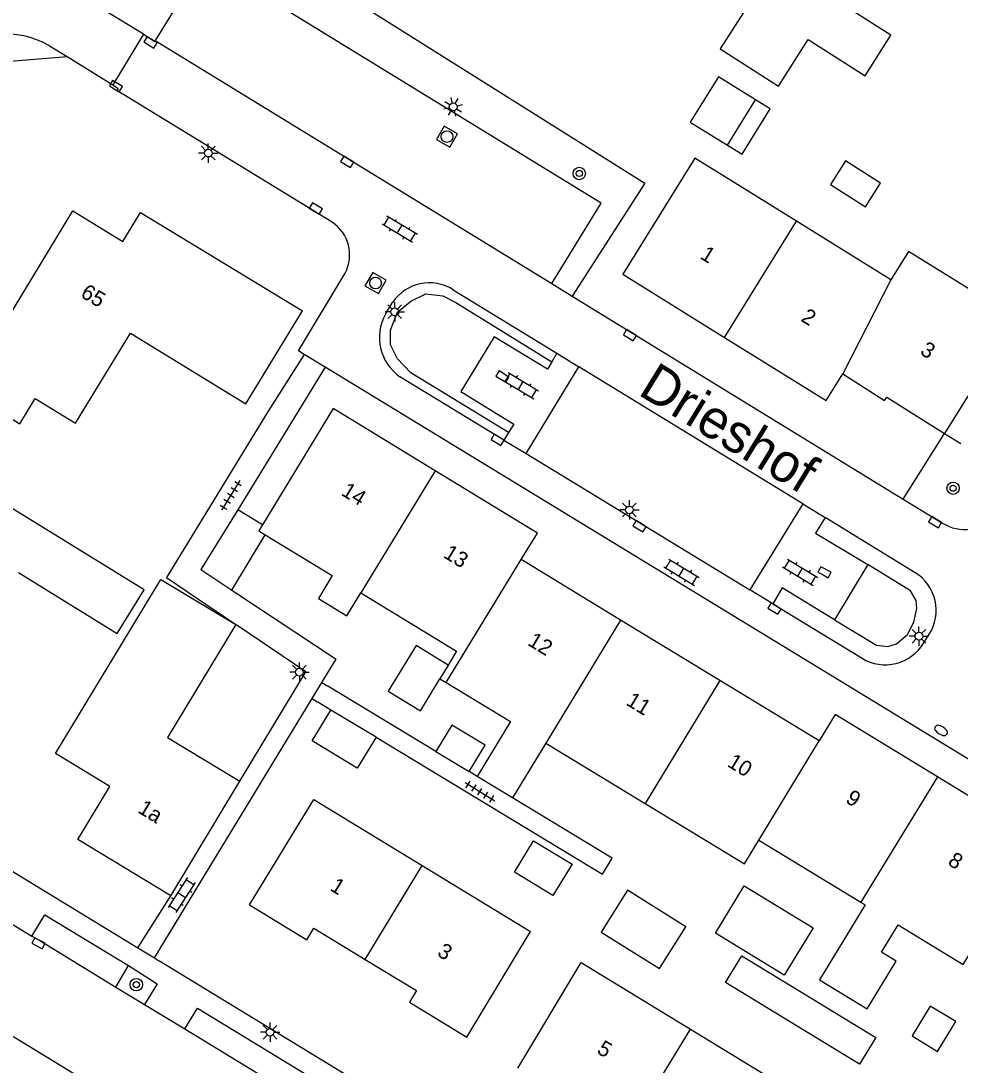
# Model space of a CAD drawing. Extents: x 136000 to 141014, y 402000 to 403500.
# Drawn here: x 137702.6 to 137763.2, y 402099.2 to 402166.6 of the extents above; entities that cross this region are included whole.
import ezdxf

# ---------------------------------------------------------------- set-up
doc = ezdxf.new("R2010")
doc.units = 0
for name, color, linetype in [('gg-afsc-erfafscheiding', 7, 'Continuous'), ('gg-afsc-muur', 7, 'Continuous'), ('gg-anno-huisnummerreeks BGT', 7, 'Continuous'), ('gg-anno-openbare ruimte label', 7, 'Continuous'), ('gg-bbg-gedigitaliseerde bebouwing', 7, 'Continuous'), ('gg-bbg-gedigitaliseerde bijgebouw', 7, 'Continuous'), ('gg-bbg-hoofdgebouw', 7, 'Continuous'), ('gg-bbg-luifel en loopbrug', 7, 'Continuous'), ('gg-bbg-tussenscheiding', 7, 'Continuous'), ('gg-knt-verharding', 7, 'Continuous'), ('gg-knt-verharding nz', 7, 'Continuous'), ('gt-grn-groengrens', 7, 'Continuous'), ('gt-symb-boom', 7, 'Continuous'), ('gt-symb-brandkraan', 7, 'Continuous'), ('gt-symb-klinker verharding', 7, 'Continuous'), ('gt-symb-kolk', 7, 'Continuous'), ('gt-symb-lichtmast', 7, 'Continuous'), ('gt-symb-rioolschacht', 7, 'Continuous'), ('gt-symb-tegel verharding', 7, 'Continuous')]:
    doc.layers.add(name, color=color, linetype=linetype)

# ---------------------------------------------------------------- blocks, each defined once
blk = doc.blocks.new('gt0-LMAST')
at = {"layer": 'gt-symb-lichtmast'}
for p, q in [((-0.182, 0.173), (-0.447, 0.438)), ((-0.005, 0.246), (-0.005, 0.621)), ((0.172, 0.173), (0.437, 0.438)), ((-0.255, -0.004), (-0.63, -0.004)), ((-0.182, -0.181), (-0.447, -0.446)), ((-0.005, -0.254), (-0.005, -0.629)), ((0.437, -0.446), (0.172, -0.181)), ((0.245, -0.004), (0.62, -0.004))]:
    blk.add_line(p, q, dxfattribs=at)
blk.add_circle((-0.005, -0.004), 0.25, dxfattribs=at)
blk = doc.blocks.new('gt0-KOLK')
at = {"layer": 'gt-symb-kolk'}
blk.add_lwpolyline([(0, 0), (0.375, 0), (0.375, 0.4), (-0.375, 0.4), (-0.375, 0), (0, 0)], dxfattribs=at)
blk = doc.blocks.new('gt0-BOOM')
at = {"layer": 'gt-symb-boom'}
for radius in [0.4, 0.2]:
    blk.add_circle((0, 0), radius, dxfattribs=at)
blk = doc.blocks.new('gt0-KL1')
at = {"layer": 'gt-symb-klinker verharding'}
for p, q in [((-1.15, 0.3), (1.15, 0.3)), ((-1, -0.3), (-1, 0.3)), ((-0.5, 0.3), (-0.5, 0.45)), ((0, -0.3), (0, 0.3)), ((0.5, 0.3), (0.5, 0.45)), ((1, -0.3), (1, 0.3)), ((-1.15, -0.3), (1.15, -0.3)), ((-0.5, -0.45), (-0.5, -0.3)), ((0.5, -0.45), (0.5, -0.3))]:
    blk.add_line(p, q, dxfattribs=at)
blk = doc.blocks.new('gt0-RS')
at = {"layer": 'gt-symb-rioolschacht'}
blk.add_lwpolyline([(-0.5, -0.5), (0.5, -0.5), (0.5, 0.5), (-0.5, 0.5)], close=True, dxfattribs=at)
blk.add_circle((0, 0), 0.375, dxfattribs=at)
blk = doc.blocks.new('gt0-TEG1')
at = {"layer": 'gt-symb-tegel verharding'}
for p, q in [((-1.125, 0), (1.125, 0)), ((-0.9, -0.25), (-0.9, 0.25)), ((-0.45, -0.25), (-0.45, 0.25)), ((0, -0.25), (0, 0.25)), ((0.45, -0.25), (0.45, 0.25)), ((0.9, -0.25), (0.9, 0.25))]:
    blk.add_line(p, q, dxfattribs=at)
blk = doc.blocks.new('gt0-BR')
at = {"layer": 'gt-symb-brandkraan'}
for centre, radius, start, end in [((-0.244, 0), 0.206, 107.56694, 252.43307), ((0.599, -2.664), 3, 106.89205, 107.56694), ((0, -0.691), 0.938, 73.10799, 106.89205), ((-0.599, -2.664), 3, 72.43309, 73.10799), ((0.244, 0), 0.206, 287.56695, 72.43309), ((0.599, 2.664), 3, 252.43307, 253.10797), ((0, 0.691), 0.938, 253.10797, 286.89206), ((-0.599, 2.664), 3, 286.89206, 287.56695)]:
    blk.add_arc(centre, radius, start, end, dxfattribs=at)

msp = doc.modelspace()

# ---------------------------------------------------------------- linework, layer by layer
at = {"layer": 'gg-afsc-erfafscheiding'}
for p, q in [((137759.538, 402135.743), (137762.2, 402139.97)), ((137722.009, 402123.896), (137722.384, 402123.668)), ((137729.368, 402119.445), (137722.384, 402123.668)), ((137721.377, 402122.858), (137721.75, 402122.631)), ((137722.594, 402122.12), (137721.75, 402122.631)), ((137732.036, 402117.837), (137731.514, 402118.146))]:
    msp.add_line(p, q, dxfattribs=at)
for points in [[(137708.781, 402177.581), (137742.867, 402156.136), (137738.168, 402148.849)], [(137725.504, 402120.36), (137740.115, 402111.522), (137740.744, 402112.563), (137734.318, 402116.45)]]:
    msp.add_lwpolyline(points, dxfattribs=at)
at = {"layer": 'gg-afsc-muur'}
msp.add_line((137718.534, 402141.413), (137711.967, 402130.672), dxfattribs=at)
msp.add_lwpolyline([(137716.722, 402117.516), (137720.971, 402124.59), (137716.45, 402127.636)], dxfattribs=at)
at = {"layer": 'gg-bbg-gedigitaliseerde bebouwing'}
for p, q in [((137758.738, 402149.902), (137752.648, 402153.682)), ((137722.73, 402141.59), (137718.165, 402134.085)), ((137729.625, 402124.145), (137730.032, 402123.898)), ((137736.467, 402119.988), (137734.318, 402116.45)), ((137736.467, 402119.988), (137742.879, 402116.092)), ((137734.318, 402116.45), (137732.036, 402117.837)), ((137750.219, 402113.707), (137756.808, 402109.703)), ((137728.493, 402112.076), (137735.475, 402107.829)), ((137756.808, 402109.703), (137757.078, 402109.539)), ((137738.758, 402105.815), (137745.816, 402101.502))]:
    msp.add_line(p, q, dxfattribs=at)
for points in [[(137752.648, 402153.682), (137746.077, 402157.76), (137741.43, 402150.26)], [(137766.83, 402147.42), (137759.877, 402151.738), (137758.738, 402149.902)], [(137697.2, 402143.82), (137702.504, 402140.61), (137703.498, 402142.239), (137706.099, 402140.651), (137709.643, 402146.457), (137717.104, 402141.903), (137720.75, 402147.89)], [(137702.415, 402131.006), (137708.801, 402127.065), (137710.537, 402129.877), (137701.28, 402135.59)], [(137718.355, 402133.436), (137722.679, 402130.808), (137721.782, 402129.332), (137723.624, 402128.213), (137724.521, 402129.689)], [(137724.521, 402129.689), (137730.709, 402125.929), (137730.16, 402125.026)], [(137730.032, 402123.898), (137734.185, 402121.374), (137732.036, 402117.837)], [(137717.34, 402109.55), (137721.498, 402116.346), (137728.493, 402112.076)], [(137742.879, 402116.092), (137749.298, 402112.192), (137750.219, 402113.707)], [(137759.21, 402108.243), (137763.417, 402105.687), (137768.35, 402113.78)], [(137757.078, 402109.539), (137754.14, 402104.702), (137757.213, 402102.835), (137759.081, 402105.909), (137758.139, 402106.48), (137759.21, 402108.243)], [(137745.816, 402101.502), (137752.819, 402097.23), (137748.66, 402090.43)]]:
    msp.add_lwpolyline(points, dxfattribs=at)
at = {"layer": 'gg-bbg-gedigitaliseerde bijgebouw'}
for p, q in [((137748.187, 402158.6), (137750.001, 402161.528)), ((137745.791, 402160.085), (137748.187, 402158.6)), ((137718.165, 402134.085), (137716.573, 402135.052)), ((137716.188, 402129.87), (137718.355, 402133.436)), ((137725.504, 402120.36), (137722.594, 402122.12)), ((137729.368, 402119.445), (137731.514, 402118.146))]:
    msp.add_line(p, q, dxfattribs=at)
for points in [[(137747.727, 402164.807), (137751.493, 402162.405), (137753.409, 402165.41), (137757.073, 402163.074), (137758.748, 402165.701), (137751.318, 402170.439), (137747.727, 402164.807)], [(137750.001, 402161.528), (137747.605, 402163.013), (137745.791, 402160.085)], [(137755.82, 402157.589), (137754.84, 402156.052), (137757.1, 402154.612), (137758.08, 402156.149), (137755.82, 402157.589)], [(137716.573, 402135.052), (137714.204, 402131.185), (137716.188, 402129.87)], [(137730.16, 402125.026), (137728.09, 402126.283), (137726.295, 402123.33), (137728.365, 402122.072), (137729.625, 402124.145)], [(137725.504, 402120.36), (137724.296, 402118.363), (137721.386, 402120.123), (137722.594, 402122.12)], [(137731.514, 402118.146), (137732.546, 402119.845), (137730.402, 402121.147), (137729.368, 402119.445)], [(137734.437, 402111.647), (137735.674, 402113.684), (137738.16, 402112.173), (137736.923, 402110.137), (137734.437, 402111.647)], [(137741.739, 402110.481), (137740.047, 402107.777), (137743.809, 402105.423), (137745.501, 402108.127), (137741.739, 402110.481)], [(137747.412, 402107.711), (137749.266, 402110.763), (137753.715, 402108.06), (137751.859, 402105.004), (137747.412, 402107.711)], [(137748.068, 402104.518), (137749.119, 402106.244), (137757.769, 402100.978), (137756.718, 402099.252), (137748.068, 402104.518)], [(137760.112, 402101.074), (137761.759, 402100.073), (137762.934, 402102.006), (137761.286, 402103.007), (137760.112, 402101.074)]]:
    msp.add_lwpolyline(points, dxfattribs=at)
at = {"layer": 'gg-bbg-hoofdgebouw'}
for p, q in [((137741.43, 402150.26), (137747.995, 402146.185)), ((137766.83, 402147.42), (137762.2, 402139.97)), ((137729.325, 402137.57), (137722.73, 402141.59)), ((137741.293, 402127.933), (137734.88, 402131.83)), ((137747.706, 402124.037), (137741.293, 402127.933)), ((137754.12, 402120.14), (137747.706, 402124.037)), ((137768.35, 402113.78), (137761.75, 402117.805)), ((137712.248, 402110.125), (137716.722, 402117.516)), ((137731.36, 402101), (137735.475, 402107.829)), ((137734.65, 402098.99), (137738.758, 402105.815))]:
    msp.add_line(p, q, dxfattribs=at)
for points in [[(137697.2, 402143.82), (137700.07, 402148.55), (137701.78, 402147.5), (137705.94, 402154.35), (137709.15, 402152.38), (137710.29, 402154.25), (137720.75, 402147.89)], [(137747.995, 402146.185), (137754.56, 402142.11), (137755.63, 402143.82)], [(137755.63, 402143.82), (137758.33, 402142.1), (137758.48, 402142.32), (137762.2, 402139.97)], [(137734.88, 402131.83), (137735.92, 402133.55), (137729.325, 402137.57)], [(137712.248, 402110.125), (137706.248, 402113.757), (137708.312, 402117.188), (137704.808, 402119.306), (137711.616, 402130.56), (137716.45, 402127.636)], [(137716.45, 402127.636), (137712.042, 402120.349), (137716.722, 402117.516)], [(137761.75, 402117.805), (137755.15, 402121.83), (137754.12, 402120.14)], [(137717.34, 402109.55), (137721.04, 402107.29), (137721.49, 402108.03), (137724.802, 402106.017)], [(137724.802, 402106.017), (137728.12, 402104), (137727.66, 402103.25), (137731.36, 402101)]]:
    msp.add_lwpolyline(points, dxfattribs=at)
at = {"layer": 'gg-bbg-luifel en loopbrug'}
msp.add_lwpolyline([(137748.187, 402158.6), (137749.14, 402158.01), (137750.954, 402160.938), (137750.001, 402161.528)], dxfattribs=at)
at = {"layer": 'gg-bbg-tussenscheiding'}
for p, q in [((137747.995, 402146.185), (137752.648, 402153.682)), ((137758.738, 402149.902), (137755.63, 402143.82)), ((137729.325, 402137.57), (137724.521, 402129.689)), ((137730.032, 402123.898), (137734.88, 402131.83)), ((137741.293, 402127.933), (137736.467, 402119.988)), ((137730.16, 402125.026), (137729.625, 402124.145)), ((137747.706, 402124.037), (137742.879, 402116.092)), ((137750.219, 402113.707), (137754.12, 402120.14)), ((137761.75, 402117.805), (137756.808, 402109.703)), ((137724.802, 402106.017), (137728.493, 402112.076)), ((137742.11, 402095.454), (137745.816, 402101.502))]:
    msp.add_line(p, q, dxfattribs=at)
msp.add_lwpolyline([(137718.165, 402134.085), (137717.928, 402133.695), (137718.355, 402133.436)], dxfattribs=at)
at = {"layer": 'gg-knt-verharding'}
for p, q in [((137710.484, 402165.757), (137707.524, 402167.564)), ((137710.484, 402165.757), (137708.513, 402162.494)), ((137705.559, 402164.312), (137708.513, 402162.494)), ((137722.666, 402153.626), (137708.781, 402162.134)), ((137736.854, 402149.655), (137738.168, 402148.849)), ((137730.489, 402149.25), (137737.17, 402145.158)), ((137738.168, 402148.849), (137759.538, 402135.743)), ((137726.109, 402147.679), (137726.57, 402148.43)), ((137720.861, 402145.084), (137718.534, 402141.413)), ((137722.213, 402144.26), (137720.861, 402145.084)), ((137737.17, 402145.158), (137736.852, 402144.609)), ((137722.213, 402144.26), (137716.573, 402135.052)), ((137735.194, 402138.676), (137738.594, 402144.286)), ((137753.057, 402135.426), (137738.594, 402144.286)), ((137733.75, 402139.557), (137727.05, 402143.64)), ((137734.057, 402140.041), (137733.75, 402139.557)), ((137735.194, 402138.676), (137749.638, 402129.874)), ((137753.057, 402135.426), (137749.638, 402129.874)), ((137759.538, 402135.743), (137762.07, 402134.19)), ((137760.3, 402130.99), (137754.493, 402134.547)), ((137757.251, 402131.513), (137755.094, 402127.95)), ((137711.967, 402130.672), (137716.45, 402127.636)), ((137716.188, 402129.87), (137722.926, 402125.403)), ((137751.114, 402128.974), (137756.88, 402125.46)), ((137760.86, 402126.45), (137761.21, 402127.011)), ((137722.009, 402123.896), (137722.926, 402125.403)), ((137721.377, 402122.858), (137722.009, 402123.896)), ((137711.195, 402106.122), (137721.377, 402122.858)), ((137688.732, 402119.823), (137710.129, 402106.77)), ((137696.701, 402111.528), (137703.294, 402107.516)), ((137710.129, 402106.77), (137712.248, 402110.125)), ((137710.129, 402106.77), (137711.195, 402106.122)), ((137708.71, 402104.22), (137709.528, 402105.613)), ((137711.195, 402106.122), (137711.532, 402105.913)), ((137785.32, 402060.9), (137711.532, 402105.913)), ((137708.71, 402104.22), (137710.56, 402103.109)), ((137713.041, 402094.346), (137698.901, 402102.965)), ((137710.56, 402103.109), (137713.151, 402101.525))]:
    msp.add_line(p, q, dxfattribs=at)
for points in [[(137736.854, 402149.655), (137740.043, 402154.855), (137714.443, 402170.555), (137711.254, 402165.355)], [(137710.484, 402165.757), (137711.229, 402165.297), (137711.254, 402165.355)], [(137679.926, 402129.217), (137689.238, 402144.751), (137688.74, 402145.096), (137696.51, 402157.968), (137700.008, 402163.88), (137705.559, 402164.312)], [(137708.513, 402162.494), (137708.865, 402162.261), (137708.781, 402162.134)], [(137720.861, 402145.084), (137720.49, 402145.31), (137723.51, 402150.33)], [(137736.852, 402144.609), (137736.578, 402144.134), (137733.121, 402146.225), (137730.987, 402142.682), (137734.399, 402140.581), (137734.057, 402140.041)], [(137764.92, 402121.99), (137772.9, 402117.11), (137771.26, 402114.36), (137722.213, 402144.26)], [(137754.493, 402134.547), (137753.885, 402133.533), (137757.251, 402131.513)], [(137755.094, 402127.95), (137751.721, 402130.008), (137751.114, 402128.974)], [(137703.294, 402107.516), (137704.123, 402108.891), (137709.528, 402105.613)], [(137709.528, 402105.613), (137711.371, 402104.448), (137710.56, 402103.109)], [(137713.151, 402101.525), (137713.969, 402102.869), (137724.512, 402096.457)]]:
    msp.add_lwpolyline(points, dxfattribs=at)
for centre, radius, start, end in [((137721.255, 402151.509), 2.545, 332.41199, 56.31399), ((137728.941, 402146.875), 2.835, 56.90018, 146.73563), ((137728.81, 402146.179), 3.089, 150.95091, 235.27857), ((137763.483, 402136.416), 2.637, 237.60587, 319.21395), ((137758.832, 402128.561), 2.838, 326.90103, 58.86305), ((137758.376, 402127.94), 2.896, 238.88953, 329.04743)]:
    msp.add_arc(centre, radius, start, end, dxfattribs=at)
at = {"layer": 'gg-knt-verharding nz'}
for p, q in [((137704.42, 402165.013), (137705.559, 402164.312)), ((137711.254, 402165.355), (137736.854, 402149.655)), ((137737.17, 402145.158), (137738.594, 402144.286)), ((137733.75, 402139.557), (137735.194, 402138.676)), ((137753.057, 402135.426), (137754.493, 402134.547)), ((137751.114, 402128.974), (137749.638, 402129.874)), ((137713.151, 402101.525), (137723.689, 402095.139))]:
    msp.add_line(p, q, dxfattribs=at)
msp.add_lwpolyline([(137703.294, 402107.516), (137703.807, 402107.24), (137708.71, 402104.22)], dxfattribs=at)
msp.add_arc((137701.452, 402159.754), 6.038, 60.56396, 127.65132, dxfattribs=at)
at = {"layer": 'gt-grn-groengrens'}
msp.add_line((137762.2, 402139.97), (137763.263, 402139.334), dxfattribs=at)
for points in [[(137734.057, 402140.041), (137727.758, 402143.896), (137726.883, 402144.802), (137726.446, 402145.709), (137726.446, 402146.647), (137726.883, 402147.804), (137727.758, 402148.523), (137728.727, 402148.992), (137729.821, 402148.867), (137730.665, 402148.43), (137736.852, 402144.609)], [(137755.094, 402127.95), (137757.823, 402126.309), (137758.542, 402126.229), (137759.101, 402126.388), (137759.82, 402126.988), (137760.219, 402127.787), (137760.419, 402128.666), (137760.379, 402129.186), (137760.019, 402129.825), (137757.251, 402131.513)]]:
    msp.add_lwpolyline(points, dxfattribs=at)

# ---------------------------------------------------------------- block references
at = {"layer": 'gt-symb-boom'}
for p in [(137738.626, 402156.768), (137762.759, 402136.445), (137710.032, 402104.387)]:
    msp.add_blockref('gt0-BOOM', p, dxfattribs=at)
at = {"layer": 'gt-symb-brandkraan', "rotation": -31.46487302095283}
msp.add_blockref('gt0-BR', (137761.978, 402120.804), dxfattribs=at)
at = {"layer": 'gt-symb-klinker verharding'}
for p, rotation in [((137727.033, 402153.176), -31.003067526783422), ((137734.855, 402143.069), -31.258485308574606), ((137745.227, 402131.019), -31.258485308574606), ((137752.891, 402131.019), -31.258485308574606), ((137712.956, 402110.179), -123.03828461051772)]:
    msp.add_blockref('gt0-KL1', p, dxfattribs=dict(at, rotation=rotation))
at = {"layer": 'gt-symb-kolk'}
for p, rotation in [((137711.05, 402165.402), 147.90821981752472), ((137708.609, 402162.24), -31.46487302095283), ((137723.541, 402157.345), -31.46487302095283), ((137721.518, 402154.332), -31.46487302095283), ((137741.795, 402146.154), -31.464873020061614), ((137733.558, 402143.485), -32.13289585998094), ((137733.46, 402139.734), 148.64043834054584), ((137761.487, 402134.076), -31.46487302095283), ((137742.614, 402134.155), 148.70547366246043), ((137754.365, 402130.844), -28.743035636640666), ((137751.336, 402128.839), 148.62934757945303), ((137703.807, 402107.24), 151.69159255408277)]:
    msp.add_blockref('gt0-KOLK', p, dxfattribs=dict(at, rotation=rotation))
at = {"layer": 'gt-symb-lichtmast', "rotation": 148.45632657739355}
msp.add_blockref('gt0-LMAST', (137730.482, 402161.071), dxfattribs=at)
at = {"layer": 'gt-symb-lichtmast'}
for p in [(137714.678, 402158.087), (137726.721, 402147.839), (137741.867, 402135.046), (137760.555, 402126.893), (137720.563, 402124.57), (137718.67, 402101.317)]:
    msp.add_blockref('gt0-LMAST', p, dxfattribs=at)
at = {"layer": 'gt-symb-rioolschacht'}
for p, rotation in [((137730.085, 402159.149), -29.794617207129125), ((137725.474, 402149.695), -29.79461720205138)]:
    msp.add_blockref('gt0-RS', p, dxfattribs=dict(at, rotation=rotation))
at = {"layer": 'gt-symb-tegel verharding'}
for p, rotation in [((137716.123, 402135.984), -121.54367342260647), ((137732.211, 402116.849), -31.543673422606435)]:
    msp.add_blockref('gt0-TEG1', p, dxfattribs=dict(at, rotation=rotation))

# ---------------------------------------------------------------- texts
at = {"layer": 'gg-anno-huisnummerreeks BGT'}
for s, rotation, p in [('1', 328.2, (137746.37, 402151.314)), ('65', 328.7, (137706.365, 402148.841)), ('2', 328.2, (137752.872, 402147.278)), ('3', 327.7, (137760.564, 402145.144)), ('14', 328.7, (137723.192, 402136.037)), ('13', 328.7, (137729.787, 402132.017)), ('12', 328.7, (137735.23, 402126.353)), ('11', 328.7, (137741.579, 402122.495)), ('10', 328.7, (137748.115, 402118.524)), ('9', 328.6, (137755.757, 402116.189)), ('1a', 328.8, (137710.06, 402115.54)), ('8', 328.6, (137762.357, 402112.164)), ('1', 328.6, (137722.472, 402110.515)), ('3', 328.7, (137729.389, 402106.295)), ('5', 328.6, (137739.703, 402100.006))]:
    msp.add_text(s, height=1, rotation=rotation, dxfattribs=at).set_placement(p)
at = {"layer": 'gg-anno-openbare ruimte label'}
msp.add_text('Drieshof', height=2.5, rotation=328.5, dxfattribs=at).set_placement((137742.345, 402142.53))

doc.saveas('drawing.dxf')
